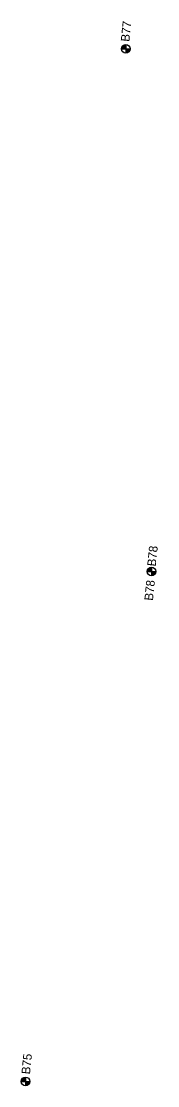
# Model space of a CAD drawing. Extents: x 345549 to 379569, y 127949 to 230467.
# Drawn here: x 359901 to 360059, y 172443 to 173673 of the extents above; entities that cross this region are included whole.
import ezdxf

# ---------------------------------------------------------------- set-up
doc = ezdxf.new("R2010")
doc.units = 0
for name, color, linetype in [('E_SOIL_BORE1 [KAPUR_CADDS_LEVELS]', 7, 'Continuous'), ('E_SOIL_BORE2 [KAPUR_CADDS_LEVELS]', 7, 'Continuous'), ('P_MARK', 7, 'Continuous')]:
    doc.layers.add(name, color=color, linetype=linetype)

msp = doc.modelspace()

# ---------------------------------------------------------------- linework, layer by layer
at = {"layer": 'P_MARK'}
for p, q in [((360017.5, 173640.8), (360027.5, 173640.8)), ((360022.5, 173645.8), (360022.5, 173635.8)), ((360047.1, 173036.8), (360057.1, 173036.8)), ((360052.1, 173041.8), (360052.1, 173031.8)), ((359901.4, 172447.6), (359911.4, 172447.6)), ((359906.4, 172452.6), (359906.4, 172442.6))]:
    msp.add_line(p, q, dxfattribs=at)
for centre in [(360022.5, 173640.8), (360052.1, 173036.8), (359906.4, 172447.6)]:
    msp.add_circle(centre, 5, dxfattribs=at)
for centre, radius, start, end in [((360022.5, 173640.8), 4.5, 89.9869, 179.9869), ((360022.5, 173640.8), 4, 89.9869, 179.9869), ((360022.5, 173640.8), 3.5, 89.9869, 179.9869), ((360022.5, 173640.8), 3, 89.9869, 179.9869), ((360022.5, 173640.8), 2.5, 89.9869, 179.9869), ((360022.5, 173640.8), 2, 89.9869, 179.9869), ((360022.5, 173640.8), 1.5, 89.9869, 179.9869), ((360022.5, 173640.8), 1, 89.9869, 179.9869), ((360022.5, 173640.8), 0.5, 89.9869, 179.9869), ((360022.5, 173640.8), 4.5, 269.9869, 359.9869), ((360022.5, 173640.8), 4, 269.9869, 359.9869), ((360022.5, 173640.8), 3.5, 269.9869, 359.9869), ((360022.5, 173640.8), 3, 269.9869, 359.9869), ((360022.5, 173640.8), 2.5, 269.9869, 359.9869), ((360022.5, 173640.8), 2, 269.9869, 359.9869), ((360022.5, 173640.8), 1.5, 269.9869, 359.9869), ((360022.5, 173640.8), 1, 269.9869, 359.9869), ((360022.5, 173640.8), 0.5, 269.9869, 359.9869), ((360052.1, 173036.8), 4.5, 89.9869, 179.9869), ((360052.1, 173036.8), 4, 89.9869, 179.9869), ((360052.1, 173036.8), 3.5, 89.9869, 179.9869), ((360052.1, 173036.8), 3, 89.9869, 179.9869), ((360052.1, 173036.8), 2.5, 89.9869, 179.9869), ((360052.1, 173036.8), 2, 89.9869, 179.9869), ((360052.1, 173036.8), 1.5, 89.9869, 179.9869), ((360052.1, 173036.8), 1, 89.9869, 179.9869), ((360052.1, 173036.8), 0.5, 89.9869, 179.9869), ((360052.1, 173036.8), 4.5, 269.9869, 359.9869), ((360052.1, 173036.8), 4, 269.9869, 359.9869), ((360052.1, 173036.8), 3.5, 269.9869, 359.9869), ((360052.1, 173036.8), 3, 269.9869, 359.9869), ((360052.1, 173036.8), 2.5, 269.9869, 359.9869), ((360052.1, 173036.8), 2, 269.9869, 359.9869), ((360052.1, 173036.8), 1.5, 269.9869, 359.9869), ((360052.1, 173036.8), 1, 269.9869, 359.9869), ((360052.1, 173036.8), 0.5, 269.9869, 359.9869), ((359906.4, 172447.6), 4.5, 89.9869, 179.9869), ((359906.4, 172447.6), 4, 89.9869, 179.9869), ((359906.4, 172447.6), 3.5, 89.9869, 179.9869), ((359906.4, 172447.6), 3, 89.9869, 179.9869), ((359906.4, 172447.6), 2.5, 89.9869, 179.9869), ((359906.4, 172447.6), 2, 89.9869, 179.9869), ((359906.4, 172447.6), 1.5, 89.9869, 179.9869), ((359906.4, 172447.6), 1, 89.9869, 179.9869), ((359906.4, 172447.6), 0.5, 89.9869, 179.9869), ((359906.4, 172447.6), 4.5, 269.9869, 359.9869), ((359906.4, 172447.6), 4, 269.9869, 359.9869), ((359906.4, 172447.6), 3.5, 269.9869, 359.9869), ((359906.4, 172447.6), 3, 269.9869, 359.9869), ((359906.4, 172447.6), 2.5, 269.9869, 359.9869), ((359906.4, 172447.6), 2, 269.9869, 359.9869), ((359906.4, 172447.6), 1.5, 269.9869, 359.9869), ((359906.4, 172447.6), 1, 269.9869, 359.9869), ((359906.4, 172447.6), 0.5, 269.9869, 359.9869)]:
    msp.add_arc(centre, radius, start, end, dxfattribs=at)

# ---------------------------------------------------------------- texts
at = {"layer": 'E_SOIL_BORE1 [KAPUR_CADDS_LEVELS]'}
for s, p in [('B77', (360026.5, 173648.6)), ('B78', (360057.1, 173042.3))]:
    msp.add_text(s, height=10, rotation=84.1728, dxfattribs=at).set_placement(p)
at = {"layer": 'E_SOIL_BORE2 [KAPUR_CADDS_LEVELS]'}
for s, p in [('B78', (360053.8, 173002.7)), ('B75', (359911.5, 172455.4))]:
    msp.add_text(s, height=10, rotation=84.1728, dxfattribs=at).set_placement(p)

doc.saveas('drawing.dxf')
